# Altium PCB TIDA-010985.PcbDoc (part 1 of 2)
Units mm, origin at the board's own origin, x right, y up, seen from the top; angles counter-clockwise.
Board outline 125.73 x 87.63 mm, 4 copper layers (Top Layer, Signal Layer 1, Signal Layer 2, Bottom Layer), stack 1.565 mm thick; 149 components, 77 nets, 379 pads, 230 vias.
Unrouted connection lines stored in the file: 1.
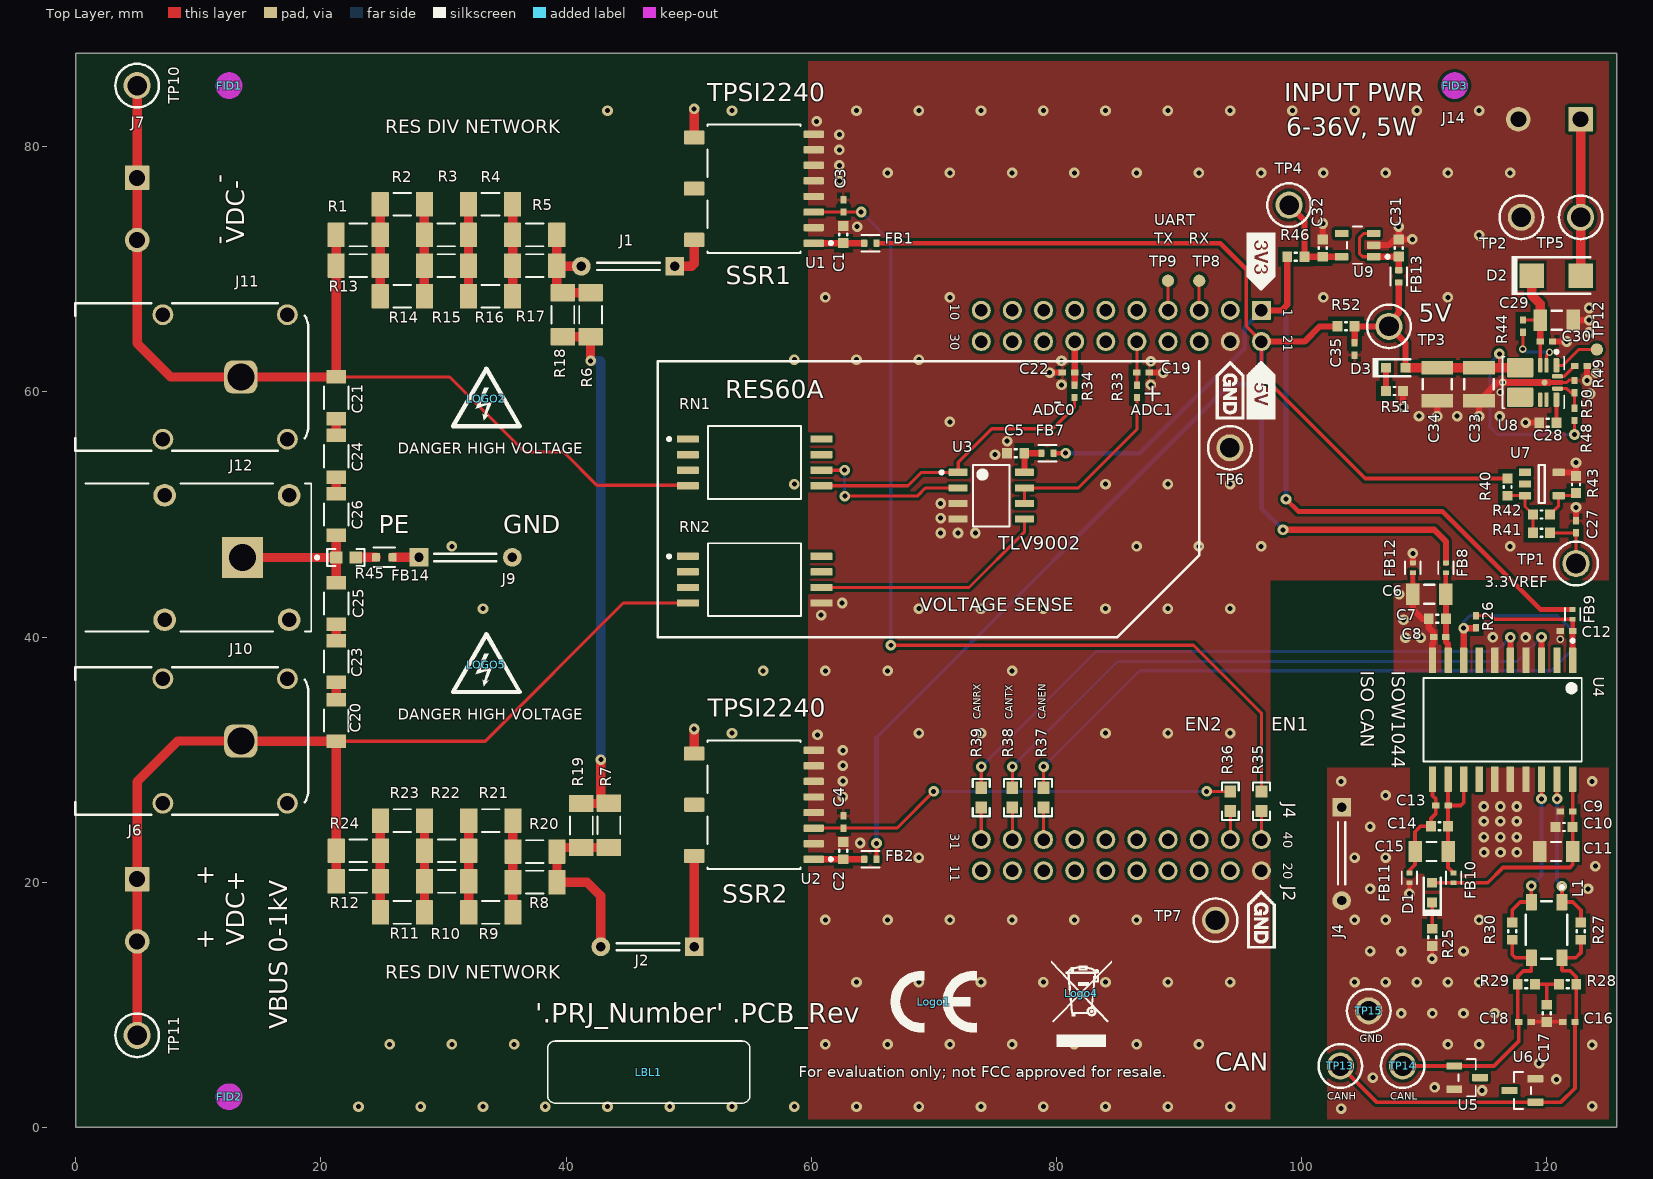
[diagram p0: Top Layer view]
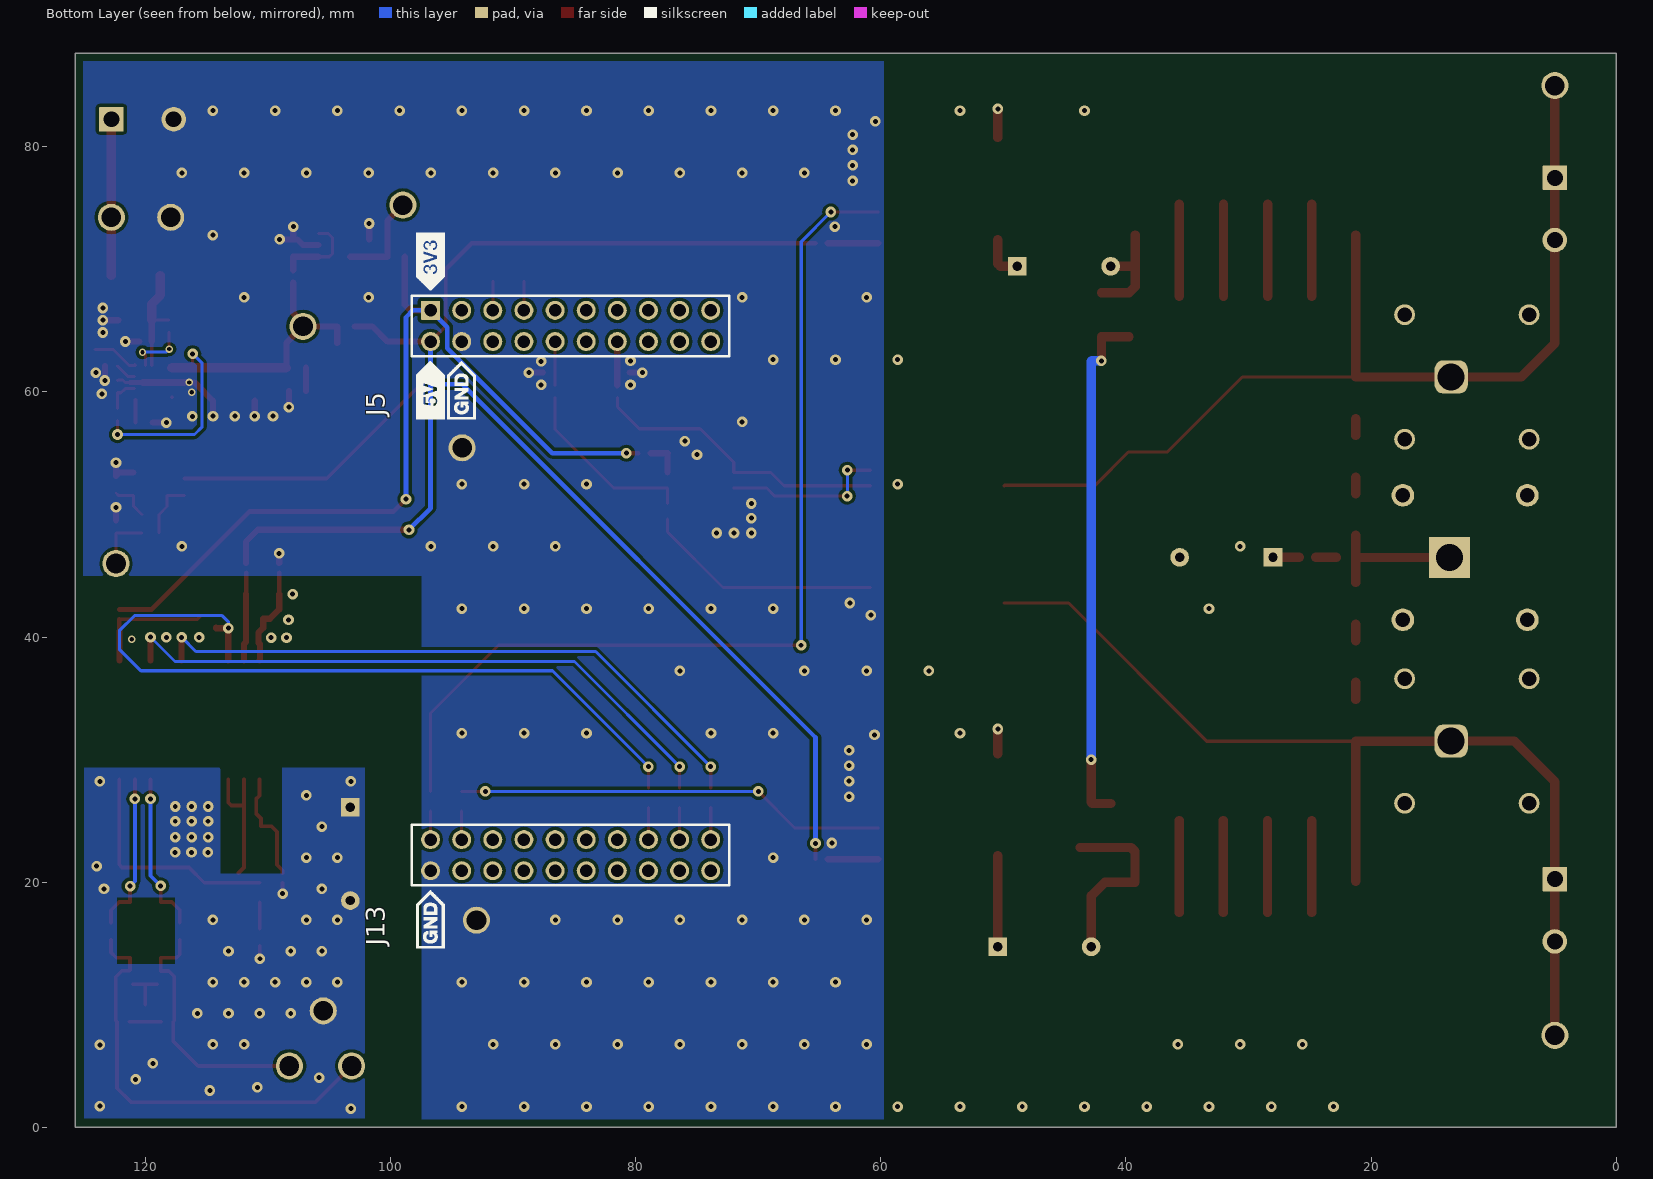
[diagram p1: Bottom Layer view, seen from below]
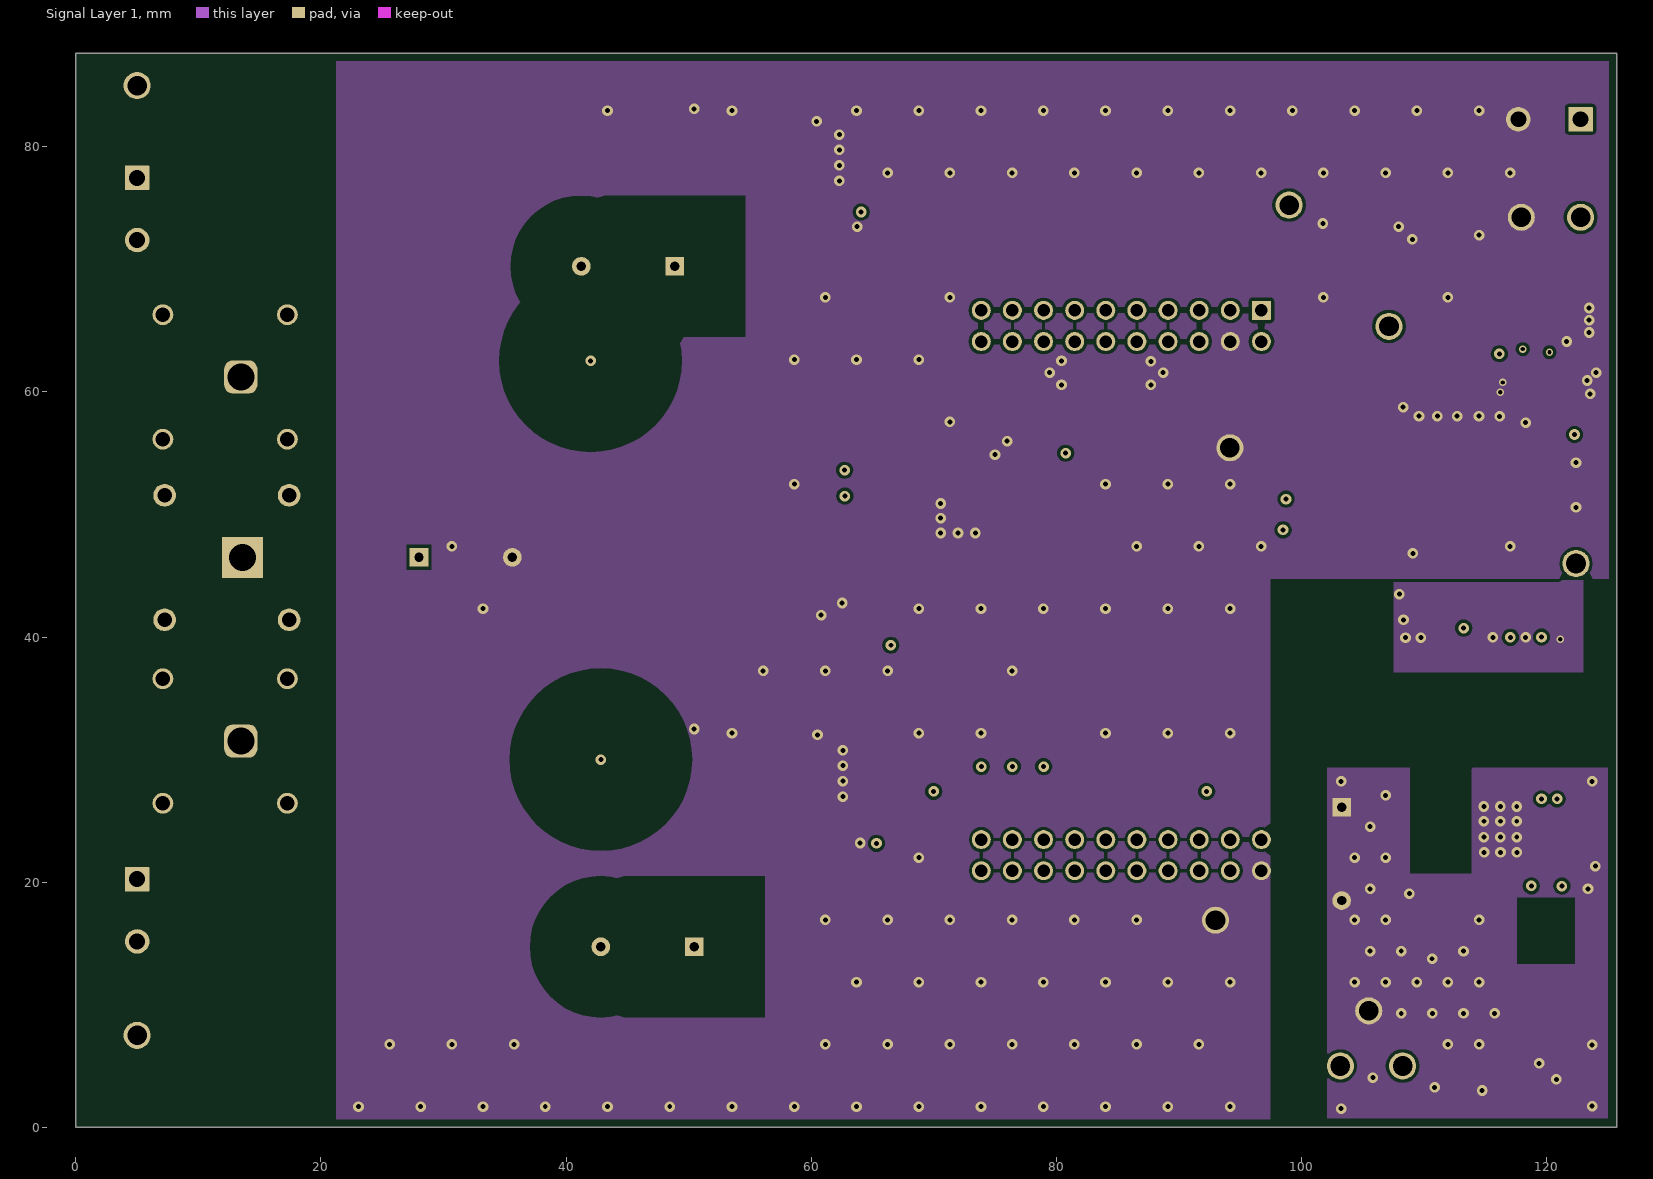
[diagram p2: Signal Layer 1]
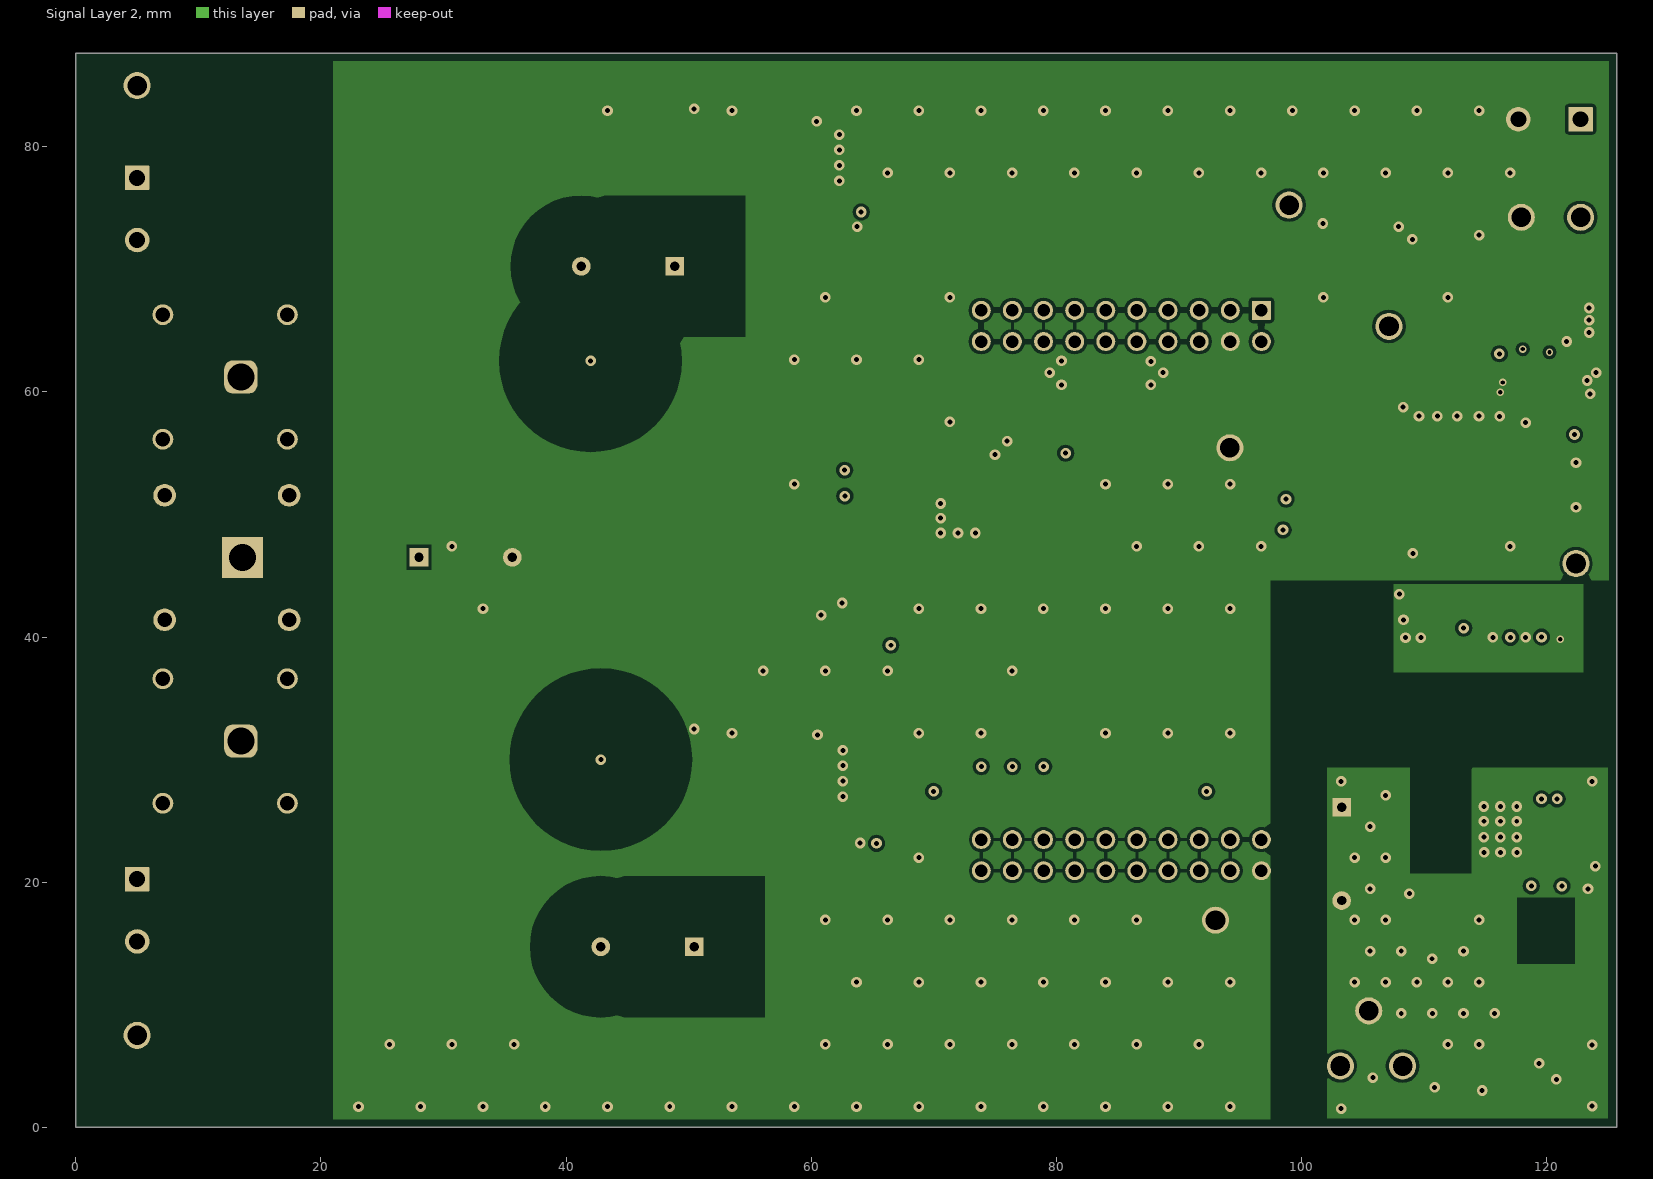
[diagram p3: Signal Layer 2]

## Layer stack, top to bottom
Top Solder: solder mask 0.0102, Solder Resist, Dk 3.5
Top Layer: signal copper 0.0356
Dielectric 1: prepreg 0.2032, FR-4 High Tg, Dk 4.2
Signal Layer 1: signal copper 0.0356
Dielectric 2: core 1.016, FR-4 High Tg, Dk 4.2
Signal Layer 2: signal copper 0.0356
Dielectric 3: prepreg 0.2032, FR-4 High Tg, Dk 4.2
Bottom Layer: signal copper 0.0356
Bottom Solder: solder mask 0.0102, Solder Resist, Dk 3.5

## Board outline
0,0 125.73,0 125.73,87.63 0,87.63

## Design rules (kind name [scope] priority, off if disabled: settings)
AcuteAngle [All] p1: minimum=4.50000000000000E+0001 checktracksonly=FALSE
AssemblyTestPointUsage [All] p1: valid=2
BoardOutlineClearance BoardOutlineClearance_MountingHoles [OnCopper and InComponentClass('Mounting Holes')] p1: gap=1 ignorepadtopadclearanceinfootprint=FALSE
BoardOutlineClearance BoardOutlineClearance_Poly [OnCopper and IsPoly] p2: gap=0.635 ignorepadtopadclearanceinfootprint=FALSE
BoardOutlineClearance [OnCopper and Not InComponentClass('Logo') and not InComponentClass('FiducialMark') and not InRegion(1000,500,4000,800) and not InPoly] p3: gap=1.016 ignorepadtopadclearanceinfootprint=FALSE
Clearance HV_HV [InNetClass('HV_Nets') vs InNetClass('HV_Nets')] p1: gap=2.2 ignorepadtopadclearanceinfootprint=TRUE
Clearance Conn_Footprint [InNetClass('HV_Nets') vs HasFootprint('Cliff_FCR7350R')or HasFootprint('Cliff_FCR7350B') or HasFootprint('FP-FCR7350G_CONN_BANANA_JACK-MFG')] p2: gap=0.6 ignorepadtopadclearanceinfootprint=TRUE
Clearance SSR_Footprint [InNetClass('HV_Nets') vs HasFootprint('dwq0011A-MFG')] p3: gap=5 ignorepadtopadclearanceinfootprint=TRUE except(3: Arc-SMDPad Track-SMDPad)
Clearance RES60_Footprint [InNetClass('HV_Nets') vs HasFootprint('dwv0008A-MFG')] p4: gap=5 ignorepadtopadclearanceinfootprint=TRUE except(0.8: Arc-SMDPad Track-SMDPad)
Clearance PE_HV [InNetClass('HV_Nets') vs InNet('PE') or InNet('PE_R')] p5: gap=2.2 ignorepadtopadclearanceinfootprint=TRUE
Clearance HV_LV [InNetClass('HV_Nets')] p6: gap=5 ignorepadtopadclearanceinfootprint=TRUE except(7: Via-Fill Via-Poly Via-Region)
Clearance Buck_Footprint [HasFootprint('rdN0011A-MFG')] p7: gap=0.114 ignorepadtopadclearanceinfootprint=TRUE
Clearance Clearance_Keepouts [((IsTrack Or IsArc) And Not InPoly) And IsFree and IsKeepOut vs ((IsTrack Or IsArc) And Not InPoly) And IsFree and IsKeepOut] p8: gap=0 ignorepadtopadclearanceinfootprint=FALSE
Clearance Clearance_Poly [InPolygon vs HasFootprint('0603L') OR HasFootprint('0402L') OR HasFootprint('0603')] p9: gap=0.254 ignorepadtopadclearanceinfootprint=TRUE except(0.381: SMDPad-Fill SMDPad-Poly SMDPad-Region)
Clearance Clearance_Poly_1 [InPolygon] p10: gap=0.254 ignorepadtopadclearanceinfootprint=TRUE
Clearance Clearance_FiducialMark [IsKeepOut and InComponentClass('FiducialMark') vs IsPad and InComponentClass('FiducialMark')] p11: gap=0 ignorepadtopadclearanceinfootprint=FALSE
Clearance [All] p12: gap=0.2 ignorepadtopadclearanceinfootprint=TRUE
ComponentClearance ComponentClearance_MountingHoles_FiducialMarks [InComponentClass('Mounting Holes') vs InComponentClass('FiducialMark')] p1: gap=1.27 collisioncheckmode=3 verticalgap=0.254 showdistances=FALSE
ComponentClearance ComponentClearance_Shunt [InComponentClass('Header') vs InComponentClass('Shunt')] p2: gap=0 collisioncheckmode=3 verticalgap=0 showdistances=FALSE
ComponentClearance ComponentClearance_Logo [InComponentClass('Logo')] p3: gap=0.762 collisioncheckmode=3 verticalgap=0.254 showdistances=FALSE
ComponentClearance ComponentClearance_ScrewToNut [(HasFootprint('NY PMS 440 0025 PH')) vs (HasFootprint('Keystone_1902C'))] p4: gap=0.127 collisioncheckmode=3 verticalgap=0.254 showdistances=FALSE
ComponentClearance ComponentClearance_MountingHoles [InComponentClass('Mounting Holes')] p5: gap=2.54 collisioncheckmode=3 verticalgap=2540 showdistances=FALSE
ComponentClearance ComponentClearance_SmallPassives [HasFootprint('0201*') or HasFootprint('0402*') or HasFootprint('0508') or HasFootprint('0603*') or HasFootprint('0612') or HasFootprint('0805*') or HasFootprint('0815*') or HasFootprint('0830*') or HasFootprint('1206*') or HasFootprint('1210*') or HasFootprint('1808*') or HasFootprint('1812*') or HasFootprint('1825*') or HasFootprint('2010*') or HasFootprint('2220*') or HasFootprint('2225*') or HasFootprint('2512*') or HasFootprint('2728*') or HasFootprint('3518*') vs HasFootprint('0201*') or HasFootprint('0402*') or HasFootprint('0508') or HasFootprint('0603*') or HasFootprint('0612') or HasFootprint('0805*') or HasFootprint('0815*') or HasFootprint('0830*') or HasFootprint('1206*') or HasFootprint('1210*') or HasFootprint('1808*') or HasFootprint('1812*') or HasFootprint('1825*') or HasFootprint('2010*') or HasFootprint('2220*') or HasFootprint('2225*') or HasFootprint('2512*') or HasFootprint('2728*') or HasFootprint('3518*')] p6: gap=0.38 collisioncheckmode=3 verticalgap=0.254 showdistances=FALSE
ComponentClearance ComponentClearance_THtoSMT [IsThruComponent vs IsSMTComponent] p7: gap=0.762 collisioncheckmode=3 verticalgap=0.762 showdistances=FALSE
ComponentClearance ComponentClearance_THtoTH [IsThruComponent vs IsThruComponent] p8: gap=0.508 collisioncheckmode=3 verticalgap=0.762 showdistances=FALSE
ComponentClearance [All] p9: gap=0.508 collisioncheckmode=3 verticalgap=0.254 showdistances=FALSE
DiffPairsRouting [All] p1: maxlimit=2.54 minlimit=0.254 mostfreqgap=0.254 toplayer_minwidth=0.381 toplayer_maxwidth=0.381 toplayer_prefwidth=0.381 midlayer1_minwidth=0.381 midlayer1_maxwidth=0.381 midlayer1_prefwidth=0.381 midlayer2_minwidth=0.381 midlayer2_maxwidth=0.381 midlayer2_prefwidth=0.381 bottomlayer_minwidth=0.381 bottomlayer_maxwidth=0.381 bottomlayer_prefwidth=0.381 maxuncoupledlength=25.4
FabricationTestPointUsage TestPointUsage [All] p1: valid=2 allowmultiple=FALSE
FabricationTestpoint Testpoint [All] p1: side=3 testpointundercomponent=TRUE minsize=1.016 maxsize=2.54 preferedsize=1.524 minholesize=0 maxholesize=1.016 preferedholesize=0.813 testpointgrid=0.025 allowsidetop=TRUE allowsidebottom=TRUE usegrid=TRUE gridtolerance=0
FanoutControl Fanout_LCC [IsLCC] p1: bgadir=Out bgaviamode=Centered fanoutstyle=Auto fanoutdirection=Alternating viagrid=0.025 // Fanout_LCC (Default Rule)
FanoutControl Fanout_BGA [IsBGA] p2: bgadir=Out bgaviamode=Centered fanoutstyle=Auto fanoutdirection=Alternating viagrid=0.025 // Fanout_BGA (Default Rule)
FanoutControl Fanout_Default [All] p4: bgadir=Out bgaviamode=Centered fanoutstyle=Auto fanoutdirection=Alternating viagrid=0.025 // Fanout_Default (Default Rule)
FanoutControl Fanout_Small [(CompPinCount < 5)] p5: bgadir=Out bgaviamode=Centered fanoutstyle=Auto fanoutdirection=OutThenIn viagrid=0.025 // Fanout_Small (Default Rule)
HoleSize [All] p1: absolutevalues=TRUE maxlimit=6.375 minlimit=0.2 maxpercent=80.000 minpercent=20.000
MinimumAnnularRing MinimumAnnularRing_ThermalPadVias [IsVia and InAnyComponent] p1: minimumring=0.15
MinimumAnnularRing [All] p2: minimumring=0.127
MinimumSolderMaskSliver MinimumSolderMaskSliver_Logo [InComponentClass('Logo') vs InComponentClass('Logo')] p1: minsoldermaskwidth=0.018
MinimumSolderMaskSliver [All] p2: minsoldermaskwidth=0.1
PlaneConnect [All] p1: planeconnectstyle=Direct reliefexpansion=0.254 reliefentries=4 reliefconductorwidth=0.254 reliefairgap=0.254
PolygonConnect PolygonConnect_1 [HasFootprint('0402L') vs InNet('GND')] p1: connectstyle=Relief reliefconductorwidth=0.254 reliefentries=4 polygonreliefangle="90 Angle" airgapwidth=0.254
PolygonConnect [All] p2: connectstyle=Direct reliefconductorwidth=0.254 reliefentries=4 polygonreliefangle="90 Angle" airgapwidth=0.254
RoutingVias ThermalPadVias [IsVia and InAnyComponent] p1: holewidth=0.2 width=0.5 viastyle="Through Hole" minholewidth=0.2 minwidth=0.5 maxholewidth=0.33 maxwidth=0.6
RoutingVias [All] p2: holewidth=0.406 width=0.864 viastyle="Through Hole" minholewidth=0.2 minwidth=0.61 maxholewidth=1.016 maxwidth=1.651
SilkToBoardRegionClearance [Not ((IsComment or IsDesignator) And (Hide <> 'False')) and not InRegion(1000,500,4000,800)] p1:
SilkToSilkClearance SilkToSilkClearance_Pb-FreeLogo [(HasFootprint('Pb-Free_Overlay_Medium') OR HasFootprint('Pb-Free_Overlay_Small')) vs (HasFootprint('Pb-Free_Overlay_Medium') OR HasFootprint('Pb-Free_Overlay_Small'))] p1: silktosilkclearance=0
SilkToSilkClearance [All] p2: silktosilkclearance=0.1
SilkToSolderMaskClearance SilkToComponentPadClearance [(IsPad or IsFill or IsRegion) and InAnycomponent] p1: minsilkscreentomaskgap=0.127 clearancetoexposedcopper=TRUE
SilkToSolderMaskClearance "Silk to Solder Mask Opening" [All] p2: minsilkscreentomaskgap=0.1 clearancetoexposedcopper=FALSE
SolderMaskExpansion [All] p1: expansion=0.05
UnRoutedNet [All] p1: checkbadconnections=TRUE
Width [All] p1: maxlimit=2.54 minlimit=0.152 preferedwidth=0.254 checkconnectedcopper=TRUE
14 further rules are at their usual default settings.

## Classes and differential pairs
net class HV_Nets: NetC20_2 NetC21_2 NetC23_2 NetC24_2 NetR1_2 NetR2_2 NetR3_2 NetR4_2 NetR6_2 NetR8_2 NetR9_2 NetR10_2 NetR11_2 S1_U1 S1_U2 VDC+ VDC- VSN_1 VSN_2
component class TIDA-010985_Connectors_Aux_PWR: C19 C20 C21 C22 C23 C24 C25 C26 C27 C28 C29 C30 C31 C32 C33 C34 C35 D2 D3 FB13 FB14 J5 J6 J7 J9 J10 J11 J12 J13 J14 R33 R34 R35 R36 R37 R38 R39 R40 R41 R42 R43 R44 R45 R46 R48 R49 R50 R51 R52 TP1 TP2 TP3 TP4 TP5 TP6 TP7 TP8 TP9 TP10 TP11 TP12 U7 U8 U9
component class TIDA-010985_CAN: C6 C7 C8 C9 C10 C11 C12 C13 C14 C15 C16 C17 C18 D1 FB8 FB9 FB10 FB11 FB12 J4 L1 R25 R26 R27 R28 R29 R30 TP13 TP14 TP15 U4 U5 U6
component class TIDA-010985_AFE: C1 C2 C3 C4 C5 FB1 FB2 FB7 J1 J2 R1 R2 R3 R4 R5 R6 R7 R8 R9 R10 R11 R12 R13 R14 R15 R16 R17 R18 R19 R20 R21 R22 R23 R24 RN1 RN2 U1 U2 U3
component class TIDA-010985_Hardware: FID1 FID2 FID3 LBL1 Logo1 LOGO2 Logo3 Logo4 LOGO5 ZZ1 ZZ2 ZZ3 ZZ4
component class FiducialMark: FID1 FID2 FID3
component class AssemblyNote: ZZ1 ZZ2 ZZ3 ZZ4
component class Label: LBL1

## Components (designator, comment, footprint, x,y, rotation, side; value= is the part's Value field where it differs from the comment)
C1 "C0603C224J3RAC7867" 0603L 62.632,72.842 r90 top value=0.22uF
C2 "C0603C224J3RAC7867" 0603L 62.632,22.57 r90 top value=0.22uF
C3 "GRM1555C1H101JA01D" 0402L 62.632,75.182 r90 top value=100pF
C4 "GRM1555C1H101JA01D" 0402L 62.632,24.91 r90 top value=100pF
C5 "C0603C224J3RAC7867" 0603L 76.693,55 r180 top value=0.22uF
C6 "CL31B106KBHNNNE" 1206_180L 110.447,43.5 r180 top value=10uF
C7 "GCM188R71C105KA64J" 0603L 111.097,41.5 r180 top value=1uF
C8 "GRM155R71H103KA88D" 0402L 111.293,40 r180 top value=0.01uF
C9 "GRM155R71E104KE14D" 0402L 121.637,25.75 r180 top value=0.1uF
C10 "GCM188R71C105KA64J" 0603L 121.437,24.5 r180 top value=1uF
C11 "CL31B106KBHNNNE" 1206_180L 120.787,22.5 r180 top value=10uF
C12 "GRM155R71E104KE14D" 0402L 121.637,40.5 r180 top value=0.1uF
C13 "GRM155R71H103KA88D" 0402L 111.477,26.25 r180 top value=0.01uF
C14 "GCM188R71C105KA64J" 0603L 111.277,24.555 r180 top value=1uF
C15 "CL31B106KBHNNNE" 1206_180L 110.627,22.5 r180 top value=10uF
C16 "C1005C0G1H680J050BA" 0402L 121.836,8.6 r180 top value=68pF
C17 "C0603X472K5RACTU" 0603L 120.016,9.3 r90 top value=4700pF
C18 "C1005C0G1H680J050BA" 0402L 118.25,8.6 r180 top value=68pF
C19 "GRM1555C1E301JA01D" 0402L 87.084,61.576 r0 top value=300pF
C20 "1206J2K00222KXR" 1206_180 21.25,33.2 r90 top value=2200pF
C21 "1206J2K00222KXR" 1206_180 21.25,59.525 r270 top value=2200pF
C22 "GRM1555C1E301JA01D" 0402L 81.004,61.576 r180 top value=300pF
C23 "1206J2K00222KXR" 1206_180 21.25,38 r90 top value=2200pF
C24 "1206J2K00222KXR" 1206_180 21.25,54.75 r270 top value=2200pF
C25 "1206J2K00222KXR" 1206_180 21.25,42.75 r90 top value=2200pF
C26 "1206J2K00222KXR" 1206_180 21.25,50 r270 top value=2200pF
C27 "GCM155R71H104KE02D" 0402L 122.412,49 r270 top value=0.1uF
C28 "GCM188R71C105KA64D" 0603L 120.112,57.5 r0 top value=1uF
C29 "CL31B106KBHNNNE" 1206_180L 120.85,65.852 r0 top value=10uF
C30 "GCM155R71H104KE02D" 0402L 120,64.116 r180 top value=0.1uF
C31 "EMK107BB7225KA-T" 0603L 107.942,71.747 r90 top value=2.2uF
C32 "EMK107BB7225KA-T" 0603L 101.75,71.738 r90 top value=2.2uF
C33 "GRM32ER71E226KE15L" 1210_270L 114.5,60.623 r270 top value=22uF
C34 "GRM32ER71E226KE15L" 1210_270L 111.092,60.623 r270 top value=22uF
C35 "GCM155R71H104KE02D" 0402L 104.35,63.502 r90 top value=0.1uF
D1 "150060VS75000" WL-SMCW_GREEN 110.672,19.15 r90 top value=Green
D2 "B160-13-F" SMA 120.79,69.5 r0 top value=60V
D3 "150060VS75000" WL-SMCW_GREEN 107.7,61.982 r0 top value=Green
FB1 "74269244182" FP-74269244182_0402-MFG 64.835,72.142 r180 top
FB2 "74269244182" FP-74269244182_0402-MFG 64.835,21.87 r180 top
FB7 "74269244182" FP-74269244182_0402-MFG 79.285,55 r180 top
FB8 "BLM15EX331SN1D" FP-BLM15EX331SN1D_0402-MFG 111.793,45.65 r270 top
FB9 "BLM15EX331SN1D" FP-BLM15EX331SN1D_0402-MFG 122.137,41.851 r270 top
FB10 "BLM15EX331SN1D" FP-BLM15EX331SN1D_0402-MFG 112.422,20.35 r270 top
FB11 "BLM15EX331SN1D" FP-BLM15EX331SN1D_0402-MFG 108.822,20.35 r270 top
FB12 "BLM15EX331SN1D" FP-BLM15EX331SN1D_0402-MFG 109.097,45.65 r270 top
FB13 "74269244182" FP-74269244182_0402-MFG 107.942,69.429 r90 top
FB14 "BLM18KG102SH1D" FP-BLM18KG102SH1D_0603-MFG 25.175,46.5 r0 top
FID1 "Fiducial" Fiducial10-20 12.5,85 r90 top
FID2 "Fiducial" Fiducial10-20 12.5,2.5 r90 top
FID3 "Fiducial" Fiducial10-20 112.5,85 r90 top
J1 "999-11-113-10-000000" Mill-Max_999-11-113-10-000000 45.06,70.25 r180 top
J2 "999-11-113-10-000000" Mill-Max_999-11-113-10-000000 46.65,14.728 r180 top
J4 "999-11-113-10-000000" Mill-Max_999-11-113-10-000000 103.292,22.308 r270 top
J5 "SSQ-110-03-T-D" BoosterPack_40pin_J1J3 85.314,65.386 r90 bottom
J6 "1888687" FP-1888687_HDR2-MFG 5,17.7 r270 top
J7 "1888687" FP-1888687_HDR2-MFG 5,74.935 r270 top
J9 "999-11-113-10-000000" Mill-Max_999-11-113-10-000000 31.81,46.5 r0 top
J10 "FCR7350R" Cliff_FCR7350R 13.46,31.515 r270 top
J11 "FCR7350B" Cliff_FCR7350B 13.46,61.225 r270 top
J12 "FCR7350G" FP-FCR7350G_CONN_BANANA_JACK-MFG 2.61,46.49 r0 top
J13 "SSQ-110-03-T-D" BoosterPack_40pin_J2J4 85.314,22.206 r90 bottom
J14 "1888687" FP-1888687_HDR2-MFG 120.25,82.25 r180 top
L1 "ACT45B-101-2P-TL003" FP-ACT45B-101-2P-TL003_SMT_4MM5_3MM2-MFG 120.016,16.099 r270 top
LBL1 "THT-14-423-10" Label_650x200 46.75,4.5 r0 top
Logo1 "CE Mark" CE_Mark_5mm 70,10.25 r0 top
LOGO2 "DANGER HIGH VOLTAGE" IEC_HighVoltage_Small 33.5,59.437 r0 top
Logo3 "FCC disclaimer" FCC_disclaimer 59.5,110.75 r0 top
Logo4 "WEEE logo" WEEE_Minimum 82.023,10.937 r0 top
LOGO5 "DANGER HIGH VOLTAGE" IEC_HighVoltage_Small 33.5,37.75 r0 top
R1 "RGV3216P-2003-B-T1" FP-RGV3216P-2003-B-T1_1206-MFG 23.04,72.81 r0 top value=200k
R2 "RGV3216P-2003-B-T1" FP-RGV3216P-2003-B-T1_1206-MFG 26.64,75.31 r0 top value=200k
R3 "RGV3216P-2003-B-T1" FP-RGV3216P-2003-B-T1_1206-MFG 30.24,72.81 r0 top value=200k
R4 "RGV3216P-2003-B-T1" FP-RGV3216P-2003-B-T1_1206-MFG 33.84,75.31 r0 top value=200k
R5 "RGV3216P-2003-B-T1" FP-RGV3216P-2003-B-T1_1206-MFG 37.44,72.81 r0 top value=200k
R6 "RGV3216P-2003-B-T1" FP-RGV3216P-2003-B-T1_1206-MFG 42,66.3 r270 top value=200k
R7 "RGV3216P-2003-B-T1" FP-RGV3216P-2003-B-T1_1206-MFG 43.5,24.635 r270 top value=200k
R8 "RGV3216P-2003-B-T1" FP-RGV3216P-2003-B-T1_1206-MFG 37.46,20 r180 top value=200k
R9 "RGV3216P-2003-B-T1" FP-RGV3216P-2003-B-T1_1206-MFG 33.86,17.526 r180 top value=200k
R10 "RGV3216P-2003-B-T1" FP-RGV3216P-2003-B-T1_1206-MFG 30.26,20.061 r180 top value=200k
R11 "RGV3216P-2003-B-T1" FP-RGV3216P-2003-B-T1_1206-MFG 26.65,17.526 r180 top value=200k
R12 "RGV3216P-2003-B-T1" FP-RGV3216P-2003-B-T1_1206-MFG 23.05,20.061 r180 top value=200k
R13 "RGV3216P-2003-B-T1" FP-RGV3216P-2003-B-T1_1206-MFG 23.04,70.31 r0 top value=200k
R14 "RGV3216P-2003-B-T1" FP-RGV3216P-2003-B-T1_1206-MFG 26.64,67.81 r0 top value=200k
R15 "RGV3216P-2003-B-T1" FP-RGV3216P-2003-B-T1_1206-MFG 30.24,70.31 r0 top value=200k
R16 "RGV3216P-2003-B-T1" FP-RGV3216P-2003-B-T1_1206-MFG 33.84,67.81 r0 top value=200k
R17 "RGV3216P-2003-B-T1" FP-RGV3216P-2003-B-T1_1206-MFG 37.44,70.31 r0 top value=200k
R18 "RGV3216P-2003-B-T1" FP-RGV3216P-2003-B-T1_1206-MFG 39.75,66.3 r270 top value=200k
R19 "RGV3216P-2003-B-T1" FP-RGV3216P-2003-B-T1_1206-MFG 41.25,24.623 r270 top value=200k
R20 "RGV3216P-2003-B-T1" FP-RGV3216P-2003-B-T1_1206-MFG 37.46,22.5 r180 top value=200k
R21 "RGV3216P-2003-B-T1" FP-RGV3216P-2003-B-T1_1206-MFG 33.86,25.026 r180 top value=200k
R22 "RGV3216P-2003-B-T1" FP-RGV3216P-2003-B-T1_1206-MFG 30.26,22.561 r180 top value=200k
R23 "RGV3216P-2003-B-T1" FP-RGV3216P-2003-B-T1_1206-MFG 26.65,25.019 r180 top value=200k
R24 "RGV3216P-2003-B-T1" FP-RGV3216P-2003-B-T1_1206-MFG 23.05,22.561 r180 top value=200k
R25 "CRCW0603499RFKEAC" 0603L 110.672,15.499 r90 top value=499
R26 "CRCW040210K0FKED" 0402L 114.25,41.25 r90 top value=10.0k
R27 "RCS06030000Z0EA" 0603L 122.816,16 r90 top value=0
R28 "RT0603DRE0759R7L" 0603L 121.738,11.672 r0 top value=59.7
R29 "RT0603DRE0759R7L" 0603L 118.356,11.672 r0 top value=59.7
R30 "RCS06030000Z0EA" 0603L 117.216,16 r90 top value=0
R33 "CRCW0402309RFKED" 0402L 86.584,60.047 r90 top value=309
R34 "CRCW0402309RFKED" 0402L 81.504,60.047 r90 top value=309
R35 "RC0603FR-071KL" 0603 96.744,26.606 r270 top value=1.00k
R36 "RC0603FR-071KL" 0603 94.204,26.606 r270 top value=1.00k
R37 "RC0603JR-070RL" 0603 78.964,26.9 r270 top value=0
R38 "RC0603JR-070RL" 0603 76.424,26.9 r270 top value=0
R39 "RC0603JR-070RL" 0603 73.884,26.9 r270 top value=0
R40 "RC0603FR-071KL" 0603L 116.824,52.238 r270 top value=1.00k
R41 "Resistor" 0603L 119.597,48.5 r180 top value=0
R42 "RT0603BRD0716K9L" 0603L 119.597,50 r180 top value=16.9k
R43 "RG1608P-103-B-T5" 0603L 122.412,52.45 r270 top value=10.0k
R44 "CRCW0402255KFKED" 0402L 118.08,65.377 r90 top value=255k
R45 "RC0603JR-070RL" 0603 22.04,46.49 r0 top value=0
R46 "RC0603JR-070RL" 0603L 99.55,71.038 r180 top value=0
R48 "CRCW04020000Z0ED" 0402L 122.292,58.173 r270 top value=0
R49 "CRCW04020000Z0ED" 0402L 122.817,62.127 r0 top value=0
R50 "CRCW04020000Z0ED" 0402L 122.292,60.433 r270 top value=0
R51 "CRCW0603499RFKEAC" 0603L 107.6,60.077 r180 top value=499
R52 "RC0603JR-070RL" 0603L 103.65,65.352 r180 top value=0
RN1 "XRES60A315QDWVRQ1" DWV0008A-MFG 55.385,54.25 r0 top
RN2 "XRES60A315QDWVRQ1" DWV0008A-MFG 55.385,44.681 r0 top
TP1 "5010" Keystone5010 122.412,46 r90 top
TP2 "5010" Keystone5010 122.79,74.25 r0 top
TP3 "5010" Keystone5010 107.15,65.352 r0 top
TP4 "5010" Keystone5010 99,75.25 r180 top
TP5 "5011" Keystone5011 117.95,74.25 r0 top
TP6 "5011" Keystone5011 94.173,55.442 r180 top
TP7 "5011" Keystone5011 93,16.895 r0 top
TP8 "TP_SM_1MM" TP_SM_1MM 91.664,69.069 r90 top
TP9 "TP_SM_1MM" TP_SM_1MM 89.124,69.069 r90 top
TP10 "5011" Keystone5011 5,85 r0 top
TP11 "5010" Keystone5010 5,7.5 r180 top
TP12 "TP_SM_1MM" TP_SM_1MM 124.114,63.459 r90 top
TP13 "5012" Keystone5012 103.184,5 r0 top
TP14 "5012" Keystone5012 108.264,5 r0 top
TP15 "5011" Keystone5011 105.5,9.5 r0 top
U1 "TPSI2140QDWQRQ1" DWQ0011A-MFG 55.335,76.587 r180 top
U2 "TPSI2140QDWQRQ1" DWQ0011A-MFG 55.335,26.315 r180 top
U3 "TLV9002QDRQ1" D0008A-MFG 74.7,51.533 r0 top
U4 "ISOW1044DFM" DFM0020A-MFG 116.422,33.25 r270 top
U5 "TSM24CADBZR" DBZ0003A-MFG 113.527,4.05 r0 top
U6 "TSM24CADBZR" DBZ0003A-MFG 118.05,3 r180 top
U7 "TLV431BIDBVR" DBV0005A_N 119.625,52.488 r0 top
U8 "TPSM33620S5QRDNRQ1" RDN0011A-MFG 118.85,60.773 r270 top
U9 "TPS7A2033PDBVR" DBV0005A-MFG 104.592,71.984 r180 top
ZZ1 "This Assembly Note is for PCB labels only" AssemblyNoteLabel 6.699,115.525 r0 top
ZZ2 "These assemblies are ESD sensitive, ESD precautions shall be observed." AssemblyNote 6.699,112.759 r0 top
ZZ3 "These assemblies must be clean and free from flux and all contaminants. Use of no clean flux is not acceptable." AssemblyNote 6.699,110.51 r0 top
ZZ4 "These assemblies must comply with workmanship standards IPC-A-610 Class 2, unless otherwise specified." AssemblyNote 6.699,108.261 r0 top

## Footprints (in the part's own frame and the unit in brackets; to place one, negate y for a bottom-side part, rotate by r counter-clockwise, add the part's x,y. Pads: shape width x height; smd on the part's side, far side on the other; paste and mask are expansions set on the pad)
0402L [mm] "0402 from SM-752 data"
  rect 0.6x0.5 smd: 1(-0.5,0) 2(0.5,0)
  body extent -0.55,-0.3 0.55,0.3, height 0.6
0603 [mm] "0603 from SM-752 data"
  rect 1x0.95 smd: 1(-0.8,0) 2(0.8,0)
  silkscreen extent -1.52,-0.69 1.52,0.69, body extent -0.87,-0.47 0.87,0.47, height 1
0603L [mm] "0603 from SM-752 data"
  rect 0.8x0.85 smd: 1(-0.7,0) 2(0.7,0)
  silkscreen extent -0.07,-0.33 0.07,0.33, body extent -0.87,-0.47 0.87,0.47, height 1
1206_180 [mm] "1206_180"
  rect 1.1x1.6 smd: 1(-1.7,0) 2(1.7,0)
  silkscreen extent -0.9,-1 0.9,1, body extent -1.75,-0.95 1.75,0.95, height 1.8
1206_180L [mm] "1206_180"
  rect 1.1x1.75 smd: 1(-1.35,0) 2(1.35,0)
  silkscreen extent -0.4,-0.77 0.4,0.77, body extent -1.75,-0.95 1.75,0.95, height 1.8
1210_270L [mm] "1210"
  rect 1.1x2.6 smd: 1(-1.35,0) 2(1.35,0)
  silkscreen extent -0.4,-1.2 0.4,1.2, body extent -1.7,-1.35 1.7,1.35, height 2.7
AssemblyNote [mm] "Assembly Note"
AssemblyNoteLabel [mm] "Assembly Note for PCB Labels"
BoosterPack_40pin_J1J3 [mm] "Receptacle, 2.54mm, 10x2, TH"
  rrect6% 1.55x1.55 hole 1.02: 1(1.27,11.43)
  round 1.55 hole 1.02: 2(1.27,8.89) 3(1.27,6.35) 4(1.27,3.81) 5(1.27,1.27) 6(1.27,-1.27) 7(1.27,-3.81) 8(1.27,-6.35) 9(1.27,-8.89) 10(1.27,-11.43) 21(-1.27,11.43) 22(-1.27,8.89) 23(-1.27,6.35) 24(-1.27,3.81) 25(-1.27,1.27) 26(-1.27,-1.27) 27(-1.27,-3.81) 28(-1.27,-6.35) 29(-1.27,-8.89) 30(-1.27,-11.43)
  silkscreen extent -7.62,-12.95 7.62,12.95, body extent -2.48,-12.95 2.48,12.95, height 8.51
BoosterPack_40pin_J2J4 [mm] "Receptacle, 2.54mm, 10x2, TH"
  round 1.55 hole 1.02: 11(-1.27,-11.43) 12(-1.27,-8.89) 13(-1.27,-6.35) 14(-1.27,-3.81) 15(-1.27,-1.27) 16(-1.27,1.27) 17(-1.27,3.81) 18(-1.27,6.35) 19(-1.27,8.89) 20(-1.27,11.43) 31(1.27,-11.43) 32(1.27,-8.89) 33(1.27,-6.35) 34(1.27,-3.81) 35(1.27,-1.27) 36(1.27,1.27) 37(1.27,3.81) 38(1.27,6.35) 39(1.27,8.89) 40(1.27,11.43)
  silkscreen extent -7.62,-12.95 2.48,12.95, body extent -2.48,-12.95 2.48,12.95, height 8.51
CE_Mark_5mm [mm] "Minimum text height for CE Mark"
  silkscreen extent -3.5,-2.5 3.5,2.5
Cliff_FCR7350B [mm] "Panel Socket, R/A, TH"
  rrect50% 2.7x2.7 hole 2.2: 1(0,0)
  round 1.7 hole 1.2: 2(-5.08,3.8) 3(5.08,3.8) 4(5.08,-6.36) 5(-5.08,-6.36)
  silkscreen extent -6.01,-13.5 6.01,5.5, body extent -6,-27.5 6,5.5, height 12.3
Cliff_FCR7350R [mm] "Panel Socket, R/A, TH"
  rrect50% 2.7x2.7 hole 2.2: 1(0,0)
  round 1.7 hole 1.2: 2(-5.08,3.8) 3(5.08,3.8) 4(5.08,-6.36) 5(-5.08,-6.36)
  silkscreen extent -6.01,-13.5 6.01,5.5, body extent -6,-27.5 6,5.5, height 12.3
D0008A-MFG [mm] "Recommended Land Pattern"
  rrect17% 1.55x0.6 smd paste+0 mask+0: 1(-2.7,1.905) 2(-2.7,0.635) 3(-2.7,-0.635) 4(-2.7,-1.905) 5(2.7,-1.905) 6(2.7,-0.635) 7(2.7,0.635) 8(2.7,1.905)
  silkscreen extent -4.17,-2.5 1.5,2.5, body extent -3,-2.45 3,2.45, height 1.75
DBV0005A-MFG [mm]
  rrect17% 1.1x0.6 smd paste+0 mask+0: 1(-1.3,0.95) 2(-1.3,0) 3(-1.3,-0.95) 4(1.3,-0.95) 5(1.3,0.95)
  silkscreen extent -2.58,-1.53 0.87,1.53, body extent -1.95,-1.78 1.95,1.78, height 0.25
DBV0005A_N [mm] "SOT23, 5-Leads, Body 2.9x1.6mm, Pitch 0.95mm, Lead Span 2.8mm, IPC Medium Density"
  rrect17% 1x0.6 smd: 1(-1.375,0.95) 2(-1.375,0) 3(-1.375,-0.95) 4(1.375,-0.95) 5(1.375,0.95)
  silkscreen extent -0.25,-1.55 0.25,1.55, body extent -1.42,-1.46 1.42,1.46, height 1.09
DBZ0003A-MFG [mm]
  rrect17% 1.3x0.6 smd paste+0 mask+0: 1(-1.05,0.95) 2(-1.05,-0.95) 3(1.05,0)
  silkscreen extent -0.7,-1.52 0.7,1.52, body extent -1.8,-1.62 1.8,1.62, height 0.25
DFM0020A-MFG [mm]
  rrect17% 2.1x0.6 smd paste+0 mask+0: 1(-4.85,5.715) 2(-4.85,4.445) 3(-4.85,3.175) 4(-4.85,1.905) 5(-4.85,0.635) 6(-4.85,-0.635) 7(-4.85,-1.905) 8(-4.85,-3.175) 9(-4.85,-4.445) 10(-4.85,-5.715) 11(4.85,-5.715) 12(4.85,-4.445) 13(4.85,-3.175) 14(4.85,-1.905) 15(4.85,-0.635) 16(4.85,0.635) 17(4.85,1.905) 18(4.85,3.175) 19(4.85,4.445) 20(4.85,5.715)
  silkscreen extent -6.57,-6.47 3.4,6.47, body extent -6,-6.72 6,6.72, height 0.25
DWQ0011A-MFG [mm]
  rrect25% 1.65x0.6 smd paste+0 mask+0: 1(-4.875,4.445) 2(-4.875,3.175) 3(-4.875,1.905) 4(-4.875,0.635) 5(-4.875,-0.635) 6(-4.875,-1.905) 7(-4.875,-3.175) 8(-4.875,-4.445)
  rrect13% 1.65x1.15 smd paste+0 mask+0: 9(4.875,-4.17) 10(4.875,0) 11(4.875,4.17)
  silkscreen extent -6.4,-5.25 3.8,5.25, body extent -5.8,-5.35 5.8,5.35, height 0.25
DWV0008A-MFG [mm] "Recommended Land Pattern"
  rrect17% 1.8x0.6 smd paste+0 mask+0: 1(-5.45,1.905) 2(-5.45,0.635) 3(-5.45,-0.635) 4(-5.45,-1.905) 5(5.45,-1.905) 6(5.45,-0.635) 7(5.45,0.635) 8(5.45,1.905)
  silkscreen extent -7.1,-2.98 3.8,2.98, body extent -5.75,-2.93 5.75,2.93, height 2.8
FCC_disclaimer [mm]
Fiducial10-20 [mm]
  round 1 smd mask+0.5: 1(0,0)
  Top Layer keep-out circle w1.178: c0,0 r0.5
FP-1888687_HDR2-MFG [mm]
  rrect5% 2x2 hole 1.3 paste-1000 mask+0: 1(-2.54,0)
  round 2 hole 1.3 paste-1000 mask+0: 2(2.54,0)
  body extent -5.26,-4.92 5.26,4.92, height 0.25
FP-74269244182_0402-MFG [mm]
  rrect20% 0.5x0.6 smd paste+0 mask+0: 1(-0.5,0) 2(0.5,0)
  silkscreen extent -0.75,-0.67 0.75,0.67, body extent -0.85,-0.4 0.85,0.4, height 0.25
FP-ACT45B-101-2P-TL003_SMT_4MM5_3MM2-MFG [mm]
  rrect11% 1.35x0.9 smd paste+0 mask+0: 1(-2.275,1.25) 2(-2.275,-1.25) 3(2.275,-1.25) 4(2.275,1.25)
  silkscreen extent -3.62,-1.7 2.35,1.7, body extent -3.05,-1.8 3.05,1.8, height 0.25
FP-BLM15EX331SN1D_0402-MFG [mm]
  rrect25% 0.4x0.5 smd paste+0 mask+0: 1(-0.4,0) 2(0.4,0)
  silkscreen extent -0.53,-0.63 0.52,0.63, body extent -0.7,-0.38 0.7,0.38, height 0.25
FP-BLM18KG102SH1D_0603-MFG [mm]
  rrect15% 0.65x0.7 smd paste+0 mask+0: 1(-0.675,0) 2(0.675,0)
  silkscreen extent -0.88,-0.78 0.87,0.8, body extent -1.1,-0.58 1.1,0.58, height 0.25
FP-FCR7350G_CONN_BANANA_JACK-MFG [mm]
  rrect3% 3.35x3.35 hole 2.2 paste-1000 mask+0: 1(11,0)
  round 1.85 hole 1.2 paste-1000 mask+0: 2(4.64,5.08) 3(14.8,5.08) 4(4.64,-5.08) 5(14.8,-5.08)
  silkscreen extent -1.83,-6.05 17.2,6.05, body extent -16.7,-6.15 16.7,6.15, height 0.25
FP-RGV3216P-2003-B-T1_1206-MFG [mm] "Recommended Land Pattern"
  rrect7% 1.4x2 smd paste+0 mask+0: 1(-1.8,0) 2(1.8,0)
  silkscreen extent -0.72,-0.92 0.72,0.92, body extent -1.6,-0.8 1.6,0.8, height 0.55
IEC_HighVoltage_Small [mm]
  silkscreen extent -2.72,-2.24 2.72,2.47
Keystone5010 [mil] "Keystone Multipurpose loops"
  round 87 hole 63: 1(0,0)
  silkscreen extent -70,-70 70,70, body extent -63,-63 63,62, height 319
Keystone5011 [mil] "Keystone Multipurpose loops"
  round 87 hole 63: 1(0,0)
  silkscreen extent -70,-70 70,70, body extent -63,-63 63,62, height 319
Keystone5012 [mil] "Keystone Multipurpose loops"
  round 87 hole 63: 1(0,0)
  silkscreen extent -70,-70 70,70, body extent -63,-63 63,62, height 319
Label_650x200 [mil] "Thermal Transfer Label"
  round 1 on Mech13: 0(0,0)
  silkscreen extent -325,-100 325,100, body extent -325,-100 325,100, height 1
Mill-Max_999-11-113-10-000000 [mil] "Shorting Jumper, 7.62mm, 2 Position, Gold, TH"
  rect 60x60 hole 30: 1(-150,0)
  round 60 hole 30: 2(150,0)
  silkscreen extent -102,-12 98,12, body extent -161,-11 161,11, height 105
RDN0011A-MFG [mm] "Recommended Land Pattern"
  rrect42% 1.2x0.475 smd paste-1000 mask-1000: 1(-1.4,1.962) 8(1.4,1.962)
  rrect57% 1.2x0.35 smd paste-1000 mask-1000: 2(-1.4,1.15) 3(-1.4,0.65) 6(1.4,0.65) 7(1.4,1.15)
  rrect13% 1.6x2.15 smd paste-1000 mask-1000: 4(-1.2,-1) 5(1.2,-1)
  rrect57% 0.35x0.9 smd paste-1000 mask-1000: 9(0.5,2.05) 11(-0.5,2.05)
  round 0.504 smd paste-1000 mask-1000: 10(0,1.005)
  Top Layer region: -0.2,2.4 -0.187,2.45 -0.15,2.487 -0.1,2.5 -0.1,2.5 0.1,2.5 0.15,2.487 0.187,2.45 0.2,2.4 0.2,2.4 0.2,1.515 0.203,1.5 0.212,1.487 0.225,1.478 0.24,1.475 0.24,1.475 0.24,1.475 0.26,1.47 0.275,1.455 0.28,1.435 0.28,1.435 0.28,-1.975 0.267,-2.025 0.23,-2.062 0.18,-2.075 0.18,-2.075 -0.18,-2.075 -0.23,-2.062 -0.267,-2.025 -0.28,-1.975 -0.28,-1.975 -0.28,1.435 -0.275,1.455 -0.26,1.47 -0.24,1.475 -0.24,1.475 -0.24,1.475 -0.225,1.478 -0.212,1.487 -0.203,1.5 -0.2,1.515 -0.2,1.515
  silkscreen extent -2.62,-2.42 2.1,2.6, body extent -1.75,-2.25 1.75,2.25, height 2.1
SMA [mm] "Molded Diode, 2-Leads, Body 4.3x2.6mm, IPC Medium Density, based on OnSemi component dimensions and land pattern"
  rect 2x2 smd: 1(-2,0) 2(2,0)
  silkscreen extent -3.66,-1.57 2.79,1.57, body extent -2.6,-1.3 2.6,1.3, height 2.42
TP_SM_1MM [mm] "1mm Test Point, SMT"
  round 1 smd paste-0.5: 1(0,0)
WEEE_Minimum [mm] "WEEElie bin"
  silkscreen extent -2.42,-4.38 2.52,2.65
WL-SMCW_GREEN [mm] "WURTH"
  rect 0.8x0.8 smd: 1(-0.8,0) 2(0.8,0)
  silkscreen extent -1.9,-0.8 1.2,0.8, body extent -0.85,-0.45 0.85,0.45, height 0.8

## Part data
C1 C2 C5: library part CMP-0006902-5, "CAP, CERM, 0.22 uF, 25 V, +/- 5%, X7R, 0603", Cap_Case=0603, Manufacturer=Kemet, Supplier Part Number 1=399-9967-1-ND, TempCo=X7R, Tolerance_%=5%, Value1=Unknown, Value2=25V, ValueDisplayed=0.22uF
C3 C4: library part CMP-0006410-2, "CAP, CERM, 100 pF, 50 V, +/- 5%, C0G/NP0, 0402", Cap_Case=0402, Manufacturer=MuRata, Supplier Part Number 1=81-GRM1555C1H101JA1D, TempCo=C0G/NP0, Tolerance_%=5%, Value1=Unknown, Value2=50V, ValueDisplayed=100pF
C6 C11 C15 C29: library part CMP-0008802-2, "CAP, CERM, 10 uF, 50 V, +/- 10%, X7R, 1206", Cap_Case=1206, Manufacturer=Samsung, Supplier Part Number 1=1276-6767-1-ND, TempCo=X7R, Tolerance_%=10%, Value1=Unknown, Value2=50V, ValueDisplayed=10uF
C7 C10 C14: library part CMP-0079154-1, "CAP, CERM, 1 µF, 16 V,+/- 10%, X7R, AEC-Q200 Grade 1, 0603", Cap_Case=0603, Manufacturer=MuRata, Supplier Part Number 1=490-12657-1-ND, TempCo=X7R, Tolerance_%=10%, Value2=16V, ValueDisplayed=1µF
C8 C13: library part CMP-0006674-2, "CAP, CERM, 0.01 uF, 50 V, +/- 10%, X7R, 0402", Cap_Case=0402, Manufacturer=MuRata, Supplier Part Number 1=490-4516-1-ND, TempCo=X7R, Tolerance_%=10%, Value1=Unknown, Value2=50V, ValueDisplayed=0.01uF
C9 C12: library part CMP-0006659-2, "CAP, CERM, 0.1 uF, 25 V, +/- 10%, X7R, 0402", Cap_Case=0402, Manufacturer=MuRata, Supplier Part Number 1=490-10698-1-ND, TempCo=X7R, Tolerance_%=10%, Value1=Unknown, Value2=25V, ValueDisplayed=0.1uF
C16 C18: library part CMP-0006251-2, "CAP, CERM, 68 pF, 50 V, +/- 5%, C0G/NP0, 0402", Cap_Case=0402, Manufacturer=TDK, Supplier Part Number 1=445-1245-1-ND, TempCo=C0G/NP0, Tolerance_%=5%, Value1=Unknown, Value2=50V, ValueDisplayed=68pF
C17: library part CMP-0006987-4, "CAP, CERM, 4700 pF, 50 V, +/- 10%, X7R, 0603", Cap_Case=0603, Manufacturer=Kemet, Supplier Part Number 1=399-5337-1-ND, TempCo=X7R, Tolerance_%=10%, Value1=Unknown, Value2=50V, ValueDisplayed=4700pF
C19 C22: library part CMP-0006376-2, "CAP, CERM, 300 pF, 25 V, +/- 5%, C0G/NP0, 0402", Cap_Case=0402, Manufacturer=MuRata, Supplier Part Number 1=GRM1555C1E301JA01D-ND, TempCo=C0G/NP0, Tolerance_%=5%, Value1=Unknown, Value2=25V, ValueDisplayed=300pF
C20 C21 C23 C24 C25 C26: library part CMP-0077201-1, "CAP, CERM, 2200 pF, 2000 V,+/- 10%, X7R, AEC-Q200 Grade 1, 1206", Cap_Case=1206, Manufacturer="Knowles Capacitors", Supplier Part Number 1=1206J2K00222KXR-ND, TempCo=X7R, Tolerance_%=10%, Value2=2000V, ValueDisplayed=2200pF
C27 C30 C35: library part CMP-0006356-2, "CAP, CERM, 0.1 uF, 50 V, +/- 10%, X7R, AEC-Q200 Grade 1, 0402", Cap_Case=0402, Manufacturer=MuRata, Supplier Part Number 1=490-10672-1-ND, TempCo=X7R, Tolerance_%=10%, Value1=Unknown, Value2=50V, ValueDisplayed=0.1uF
C28: library part CMP-0007136-5, "CAP, CERM, 1 uF, 16 V, +/- 10%, X7R, AEC-Q200 Grade 1, 0603", Cap_Case=0603, Manufacturer=MuRata, Supplier Part Number 1=490-5241-6-ND, TempCo=X7R, Tolerance_%=10%, Value1=Unknown, Value2=16V, ValueDisplayed=1uF
C31 C32: library part CMP-0007121-4, "CAP, CERM, 2.2 uF, 16 V, +/- 10%, X7R, 0603", Cap_Case=0603, Manufacturer="Taiyo Yuden", Supplier Part Number 1=EMK107BB7225KA-T-ND, TempCo=X7R, Tolerance_%=10%, Value1=Unknown, Value2=16V, ValueDisplayed=2.2uF
C33 C34: library part CMP-0009224-2, "CAP, CERM, 22 uF, 25 V, +/- 10%, X7R, 1210", Cap_Case=1210, Manufacturer=MuRata, Supplier Part Number 1=490-5313-1-ND, TempCo=X7R, Tolerance_%=10%, Value1=Unknown, Value2=25V, ValueDisplayed=22uF
D1 D3: library part CMP-0002894-2, "LED, Green, SMD", Color=green, Manufacturer="Wurth Elektronik", Value1=W, Value2=2V
D2: library part CMP-0028389-2, "Diode, Schottky, 60 V, 1 A, SMA", Manufacturer="Diodes Inc.", Value1=1A, Value2=0.7V
FB1 FB2 FB7 FB13: library part CMP-0091663-1, "1.8 kOhms @ 100MHz 1 Power, Signal Line Ferrite Bead 0402 (1005 Metric) 210mA 2.1Ohm", Digikey Part Number=732-74269244182CT-ND, Impedance At Frequency="1800O @ 100MHz", Manufacturer="Wurth Electronics", Mouser Part Number=710-74269244182, Operating Temperature Range="-55°C to +125°C", Test Frequency=1GHz, Tolerance_%=25%
FB8 FB9 FB10 FB11 FB12: library part CMP-0041881-1, "Chip Ferrite Bead, 0402, 330O @ 100MHz, 0.205O, 25%, 1.1A", Impedance At Frequency="330O @ 100MHz", Manufacturer=Murata, Operating Temperature Range="-55°C to +125°C", Test Frequency=100MHz, Tolerance_%=25%
FB14: library part CMP-0089381-1, "1 kOhms @ 100MHz 1 Power Line Ferrite Bead 0603 (1608 Metric) 1A 200mOhm", Digikey Part Number=490-17348-1-ND, Impedance At Frequency="1kO @ 100MHz", Manufacturer=Murata, Mouser Part Number=81-BLM18KG102SH1D, Operating Temperature Range="-55°C to +125°C", Test Frequency=100MHz, Tolerance_%=25%
FID1 FID2 FID3: library part CMP-0077181-1, "Fiducial mark.  There is nothing to buy or mount.", Manufacturer=N/A
J1 J2 J4 J9: library part CMP-0055045-1, "Shorting Jumper, 7.62mm, 2 Position, Gold, TH", Manufacturer=Mill-Max, Supplier Part Number 1=ED1334-ND
J5: library part CMP-0003837-4, "Receptacle, 2.54mm, 10x2, Tin, TH", Alternate Manufacturer="Major League Electronics", Alternate PartNumber=CRD-081413-A-G, Manufacturer=Samtec, Supplier Part Number 1=SAM1204-10-ND
J6 J7 J14: library part CMP-0087130-1, Current_A=16A, Manufacturer="Phoenix Contact", Voltage_V=400V
J10: library part CMP-0055799-1, "Panel Socket, 24A, R/A, Gold, TH", Color=Red, Current_A=24A, Manufacturer="Cliff Electronic Components", Supplier Part Number 1=20T2058, Voltage_V=1kV
J11: library part CMP-0055798-1, "Panel Socket, 24A, R/A, Gold, TH", Color=Black, Current_A=24A, Manufacturer="Cliff Electronic Components", Supplier Part Number 1=20T2055, Voltage_V=1kV
J12: library part CMP-0098294-2, "Banana Test Connector, Socket, PCB Mount, 24 A, 1 kV, Gold Plated Contacts, Green", Current_A=24A, Digikey Part Number=4654-FCR7350G-ND, Manufacturer="CLIFF Electronic Components", Operating Temperature Range="-40°C to +80°C", Voltage_V=1kV
J13: library part CMP-0078266-4, "Receptacle, 2.54mm, 10x2, Tin, TH", Alternate Manufacturer="Major League Electronics", Alternate PartNumber=CRD-081413-A-G, Manufacturer=Samtec, Supplier Part Number 1=SAM1204-10-ND
L1: library part CMP-0084086-1, "100µH @ 100kHz 2 Line Common Mode Choke Surface Mount 5.8 kOhms @ 10MHz 150mA DCR 2Ohm", Digikey Part Number=445-3959-1-ND, Impedance At Frequency="5800O @ 10MHz", Manufacturer=TDK, Mouser Part Number=810-ACT45B1012PTL003, Operating Temperature Range="-40°C to +150°C", Test Frequency=100kHz, Tolerance_%=+50/-30%
LBL1: library part CMP-0003625-1, "Thermal Transfer Printable Labels, 0.650\" W x 0.200\" H - 10,000 per roll", Manufacturer=Brady, Supplier Part Number 1=97C5133
Logo1: library part CMP-0074844-2, Manufacturer="Texas Instruments"
LOGO2 LOGO5: library part CMP-0074835-1, "IEC 61010-1 High Voltage Warning"
Logo3: library part CMP-0074847-1, "FCC_disclaimer"
Logo4: library part CMP-0074769-4, Manufacturer="Texas Instruments"
R1 R2 R3 R4 R5 R6 R7 R8 R9 R10 R11 R12 R13 R14 R15 R16 R17 R18 R19 R20 R21 R22 R23 R24: library part CMP-0126488-1, "200 kOhms ±0.1% 0.25W, 1/4W Chip Resistor 1206 (3216 Metric) Anti-Sulfur, Automotive AEC-Q200, High Voltage Thin Film", Digikey Part Number=408-RGV3216P-2003-B-T1CT-ND, Manufacturer=Susumu, Mouser Part Number=754-RGV3216P-2003BT1, Operating Temperature Range="-55°C to +155°C", Power_W=250mW, TempCo=25ppm/°C, Tolerance_%=0.1%
R25 R51: library part CMP-0082532-1, "RES, 499, 1%, 0.1 W, 0603", Manufacturer=Vishay-Dale, Power_W=100mW, Supplier Part Number 1=541-3986-1-ND, TempCo="100 ppm/C", Tolerance_%=1%, Value2=0.1W, Value_Code=499R, ValueDisplayed=499
R26: library part CMP-0025958-3, "RES, 10.0 k, 1%, 0.063 W, AEC-Q200 Grade 0, 0402", Manufacturer=Vishay-Dale, Power_W=63mW, Supplier Part Number 1=541-10.0KLCT-ND, TempCo="100 ppm/C", Tolerance_%=1%, Value2=0.063W, Value_Code=10k0, ValueDisplayed=10.0k
R27 R30: library part CMP-0081973-1, "RES, 0, 0%, 0.25 W, AEC-Q200 Grade 0, 0603", Manufacturer=Vishay-Dale, Power_W=250mW, Supplier Part Number 1=541-2779-1-ND, Tolerance_%=0%, Value2=0.25W, Value_Code=0
R28 R29: library part CMP-0025431-3, "RES, 59.7, 0.5%, 0.1 W, 0603", Manufacturer="Yageo America", Power_W=100mW, TempCo="50 ppm/C", Tolerance_%=0.5%, Value2=0.1W, Value_Code=59R7, ValueDisplayed=59.7
R33 R34: library part CMP-0026283-2, "RES, 309, 1%, 0.063 W, AEC-Q200 Grade 0, 0402", Manufacturer=Vishay-Dale, Power_W=63mW, Supplier Part Number 1=541-309LCT-ND, TempCo="100 ppm/C", Tolerance_%=1%, Value2=0.063W, Value_Code=309R, ValueDisplayed=309
R35 R36 R40: library part CMP-0022895-5, "RES, 1.00 k, 1%, 0.1 W, 0603", Manufacturer=Yageo, Power_W=100mW, Supplier Part Number 1=311-1.00KHRCT-ND, TempCo="100 ppm/C", Tolerance_%=1%, Value2=0.1W, Value_Code=1k00, ValueDisplayed=1.00k
R37 R38 R39 R45 R46 R52: library part CMP-0025885-5, "RES, 0, 5%, 0.1 W, 0603", Manufacturer=Yageo, Power_W=100mW, Supplier Part Number 1=311-0.0GRCT-ND, TempCo="200 ppm/C", Tolerance_%=5%, Value2=0.1W, Value_Code=0000, ValueDisplayed=0
R41: library part CMP-0025697-4, "RES, 0, 5%, 0.1 W, AEC-Q200 Grade 0, 0603", Manufacturer=Vishay-Dale, PartNumber=CRCW06030000Z0EA, Power_W=100mW, Supplier Part Number 1=541-0.0GCT-ND, TempCo="200 ppm/C", Tolerance_%=5%, Value2=0.1W, Value_Code=0000, ValueDisplayed=0
R42: library part CMP-0023802-3, "RES, 16.9 k, 0.1%, 0.1 W, 0603", Manufacturer="Yageo America", Power_W=100mW, TempCo="25 ppm/C", Tolerance_%=0.1%, Value2=0.1W, Value_Code=16k9, ValueDisplayed=16.9k
R43: library part CMP-0023404-3, "RES, 10.0 k, 0.1%, 0.1 W, 0603", Manufacturer="Susumu Co Ltd", Power_W=100mW, Supplier Part Number 1=RG16P10.0KBCT-ND, TempCo="25 ppm/C", Tolerance_%=0.1%, Value2=0.1W, Value_Code=10k0, ValueDisplayed=10.0k
R44: library part CMP-0026199-2, "RES, 255 k, 1%, 0.063 W, AEC-Q200 Grade 0, 0402", Manufacturer=Vishay-Dale, Power_W=63mW, Supplier Part Number 1=541-255KLCT-ND, TempCo="100 ppm/C", Tolerance_%=1%, Value2=0.063W, Value_Code=255k
R48 R49 R50: library part CMP-0026822-3, "RES, 0, 5%, 0.063 W, AEC-Q200 Grade 0, 0402", Manufacturer=Vishay-Dale, Power_W=63mW, Supplier Part Number 1=541-0.0JCT-ND, TempCo="200 ppm/C", Tolerance_%=5%, Value2=0.063W, Value_Code=0000, ValueDisplayed=0
RN1 RN2: library part CMP-0126545-1, Manufacturer="Texas Instruments", Operating Temperature Range=to
TP1 TP2 TP3 TP4 TP11: library part CMP-0055147-2, "Test Point, Multipurpose, Red, TH", Color=Red, Manufacturer="Keystone Electronics", Supplier Part Number 1=36-5010-ND
TP5 TP6 TP7 TP10 TP15: library part CMP-0055148-2, "Test Point, Multipurpose, Black, TH", Color=Black, Manufacturer="Keystone Electronics", Supplier Part Number 1=36-5011-ND
TP8 TP9 TP12: library part CMP-0003825-1, "1mm Test Point, SMT", Manufacturer=Any
TP13 TP14: library part CMP-0055149-2, "Test Point, Multipurpose, White, TH", Color=White, Manufacturer="Keystone Electronics", Supplier Part Number 1=36-5012-ND
U1 U2: library part CMP-0090961-3, "Isolated Solid State Relay", Manufacturer="Texas Instruments", On State Resistance=85O, Operating Temperature Range="-40°C to +150°C", Output Voltage=1400V, Voltage_Isolation_Vrms=1414VDC
U3: library part CMP-0126497-1, "Automotive-grade, dual, 5.5-V, 1-MHz, RRIO operational amplifier for cost-optimized applications 8-SOIC -40 to 125", Digikey Part Number=296-TLV9002QDRQ1CT-ND, Input Bias Current=5pA, Input Offset Voltage=0.4mV, Manufacturer="Texas Instruments", Max Dual Supply Voltage=2.75V, Max Supply Voltage=5.5V, Min Dual Supply Voltage=900mV, Min Supply Voltage=1.8V, Mouser Part Number=595-TLV9002QDRQ1, Nominal Supply Current=60uA, Operating Temperature Range="-40°C to +125°C", Output Current Per Channel=40mA, Voltage Gain=130dB
U4: library part CMP-0092023-2, "Reinforced 5-kVRMS Isolated CAN Transceiver with Integrated lowemissions DC-DC Converter", Manufacturer="Texas Instruments", Max Supply Voltage=5.5V, Min Supply Voltage=1.71V, Nominal Supply Current=0.3-124mA, Operating Temperature Range="-40°C to +105°C"
U5 U6: library part CMP-0120116-1, "±24 V Low Capacitance Surge Diode for Industrial Networks in SOT-23 Package", Breakdown Voltage=25.5V, Clamping Voltage=35V, Digikey Part Number=296-TSM24CADBZRCT-ND, Manufacturer="Texas Instruments", Mouser Part Number=595-TSM24CADBZR, Operating Temperature Range="-55°C to +150°C", ValueDisplayed=14pF
U7: library part CMP-0032881-1, "Low-Voltage Adjustable Precision Shunt Regulator, 15 mA, -40 to 85 degC, 5-pin SOT-23 (DBV), Green (RoHS & no Sb/Br)", Manufacturer="Texas Instruments", Rating=Catalog, Temp Coeff(Max)(ppm/ degree C)=129
U8: library part CMP-0126544-1, "Automotive, 3V to 36V Input, 1V to 7V Output, 2A, Synchronous Buck Converter Power Module, QFN-FCMOD11", Manufacturer="Texas Instruments", Max Supply Voltage=36V, Min Supply Voltage=3V, Nominal Supply Current=1.2uA, Operating Temperature Range="-40°C to +150°C", Output Voltage=5/1-7V, Switching Frequency=2.2MHz
U9: library part CMP-0092532-1, "300-mA, Ultra-Low-Noise, Low-IQ, High PSRR LDO", Digikey Part Number=296-TPS7A2033PDBVRCT-ND, Dropout Voltage=145mV, Manufacturer="Texas Instruments", Max Supply Voltage=6V, Min Supply Voltage=1.6V, Mouser Part Number=595-TPS7A2033PDBVR, Nominal Supply Current=6.5uA, Operating Temperature Range="-40°C to +125°C", Output Voltage=3.3V
ZZ1: library part CMP-0003616-3
ZZ2: library part CMP-0077236-1
ZZ3: library part CMP-0077237-1
ZZ4: library part CMP-0077238-1

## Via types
v1: diameter 0.864, hole 0.406, Top Layer to Bottom Layer, tented both sides, 225 vias
v2: diameter 0.61, hole 0.356, Top Layer to Bottom Layer, tented both sides, 5 vias

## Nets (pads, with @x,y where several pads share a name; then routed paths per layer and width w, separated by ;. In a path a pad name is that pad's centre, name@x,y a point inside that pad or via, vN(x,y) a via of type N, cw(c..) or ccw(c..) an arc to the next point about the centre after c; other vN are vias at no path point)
3V3: FB7.1 FB9.1 J5.1 R46.2 | length 73.2
  Top Layer w0.381: FB7.1@79.785,55 v1(80.77,55) ; v1(98.75,51.25) 99.75,50.25 111.5,50.25 119.499,42.251 FB9.1@122.137,42.251
  Top Layer w0.508: J5.1@96.744,66.656 98.395,66.656 98.85,67.111 R46.2@98.85,71.038
  Bottom Layer w0.381: v1(80.77,55) 86.807,55 95.37,63.563 95.37,65.282 J5.1@96.744,66.656 98.198,66.656 98.75,66.104 v1(98.75,51.25)
431VREF: R42.1 R43.2 U7.4 | length 3.3
  Top Layer w0.254: R42.1@120.297,50 121,50.703 U7.4@121,51.538 122.2,51.538 R43.2@122.412,51.75
+5V: FB1.1 FB2.1 FB8.1 J5.21 R40.1 R52.2 | length 155.3
  Top Layer w0.305: FB2.1@65.335,21.87 v1(65.335,23.168) ; 95.5,70.021 95.5,65.36 J5.21@96.744,64.116 96.744,61.411 105.217,52.938 R40.1@116.824,52.938
  Top Layer w0.381: FB1.1@65.335,72.142 93.379,72.142 95.5,70.021
  Top Layer w0.508: J5.21@96.744,64.116 100.264,64.116 101.5,65.352 R52.2@102.95,65.352 ; v1(98.506,48.75) 110.85,48.75 111.793,47.807 FB8.1@111.793,46.05
  Bottom Layer w0.381: v1(65.335,23.168) 65.335,31.802 94.169,60.636 96.744,60.636 ; J5.21@96.744,64.116 96.744,60.636 ; v1(98.506,48.75) 96.744,50.512 96.744,60.636
AUX_PWR: D2.2 J14.1 TP2.1 | length 12.7
  Top Layer w0.762: D2.2@122.79,69.5 122.79,74.75 J14.1@122.79,82.25
BUCK_EN: R44.1 U8.2 | length 4.8
  Top Layer w0.254: v2(118.08,63.5) R44.1@118.08,64.877 ; U8.2@120,62.173 120,63 v2(120.25,63.25)
  Bottom Layer w0.254: v2(118.08,63.5) 118.33,63.25 v2(120.25,63.25)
